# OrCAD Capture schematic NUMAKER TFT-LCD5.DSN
size A4; title: NuMaker TFT-LCD5; rev: 1.0; company: nuvoTon Technology Corp.; note: LCD
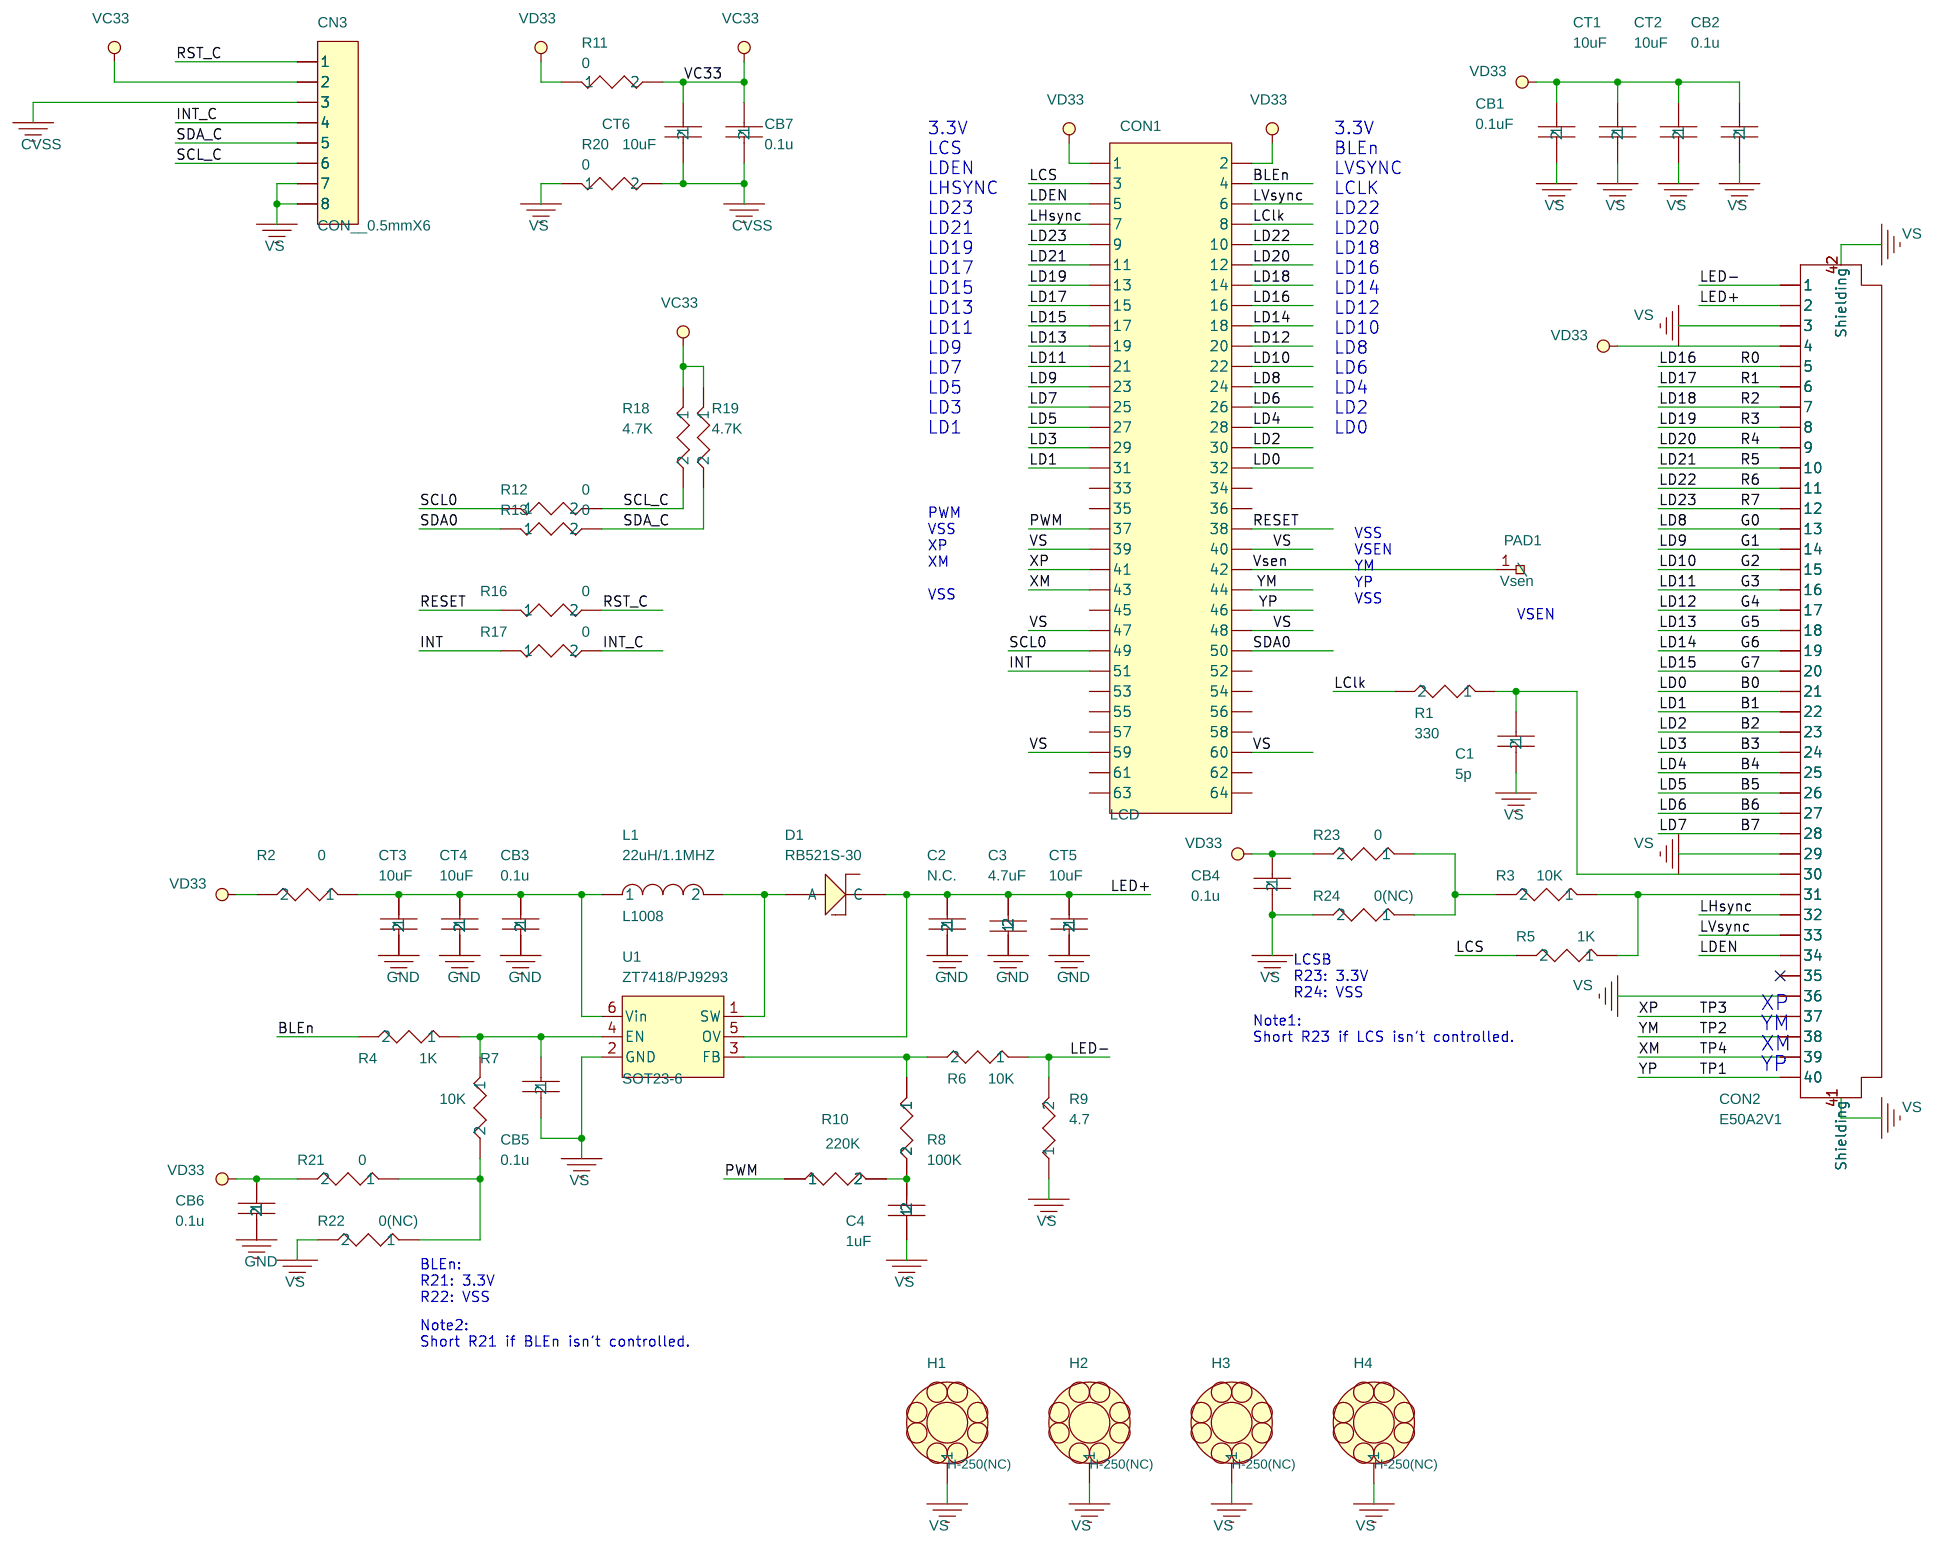
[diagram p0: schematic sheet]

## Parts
C1  5p  [C0603]
C2  N.C.  [C0603]
C3  4.7uF  [C0603]
C4  1uF  [C0603]
CB1  0.1uF  [C0603]
CB2  0.1u  [C0603]
CB3  0.1u  [C0603]
CB4  0.1u  [C0603]
CB5  0.1u  [C0603]
CB6  0.1u  [C0603]
CB7  0.1u  [C0603]
CN3  CON__0.5mmX6  [CON_0.5MMX6]
CON1  LCD  [F_DIN_32X2/2.54A]
CON2  E50A2V1  [CON0.5mmx40]
CT1  10uF  [C0603]
CT2  10uF  [C0603]
CT3  10uF  [C0603]
CT4  10uF  [C0603]
CT5  10uF  [C0603]
CT6  10uF  [C0603]
D1  RB521S-30  [Diode_A]
H1  H-250(NC)  [H-250]
H2  H-250(NC)  [H-250]
H3  H-250(NC)  [H-250]
H4  H-250(NC)  [H-250]
L1  22uH/1.1MHZ  [L1008]
PAD1  Vsen  [1PAD_1.25X1.25MM]
R1  330  [R0603]
R2  0  [R0603]
R3  10K  [R0603]
R4  1K  [R0603]
R5  1K  [R0603]
R6  10K  [R0603]
R7  10K  [R0603]
R8  100K  [R0603]
R9  4.7  [R0603]
R10  220K  [R0603]
R11  0  [R0603]
R12  0  [R0603]
R13  0  [R0603]
R16  0  [R0603]
R17  0  [R0603]
R18  4.7K  [R0603]
R19  4.7K  [R0603]
R20  0  [R0603]
R21  0  [R0603]
R22  0(NC)  [R0603]
R23  0  [R0603]
R24  0(NC)  [R0603]
U1  ZT7418/PJ9293  [SOT23-6]

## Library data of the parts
C1 = CAP-B_2: Package: 0603
C2 = CAP-B_5: Package: C0402
C3 = CAP_NP_6
C4 = CAP_NP_4
CB1 = CAP_NP
CB2 = CAP_NP_9
CB3 = CAP-B_3: Package: C0402
CB4 = CAP-B: Package: C0402
CB5 = CAP-B_1: Package: C0402
CB6 = CAP-B_4: Package: C0402
CB7 = CAP_NP_2
CN3 = CON8
CON1 = CON40A_0
CON2 = LCMCON40x1
CT1 = CAP_NP_8
CT2 = CAP_NP_3
CT3 = CAP_NP_7
CT4 = CAP_NP_1
CT5 = CAP-B_6: Package: C0402
CT6 = CAP_NP_5
D1 = ZENAR_0: Package: D
H1-H4 = T_POINT_2
L1 = INDUCTOR: Package: L-3
PAD1 = 1PAD_0
R1 = R
R2 = R_12: Package: R0402
R3 = R_20: Package: R0402
R4 = R_10: Package: R0402
R5 = R_14: Package: R0402
R6 = R_13: Package: R0402
R7 = R_2: Package: R0402
R8 = R_3
R9 = R_1: Package: R0402
R10 = R_9
R11 = R_8
R12 = R_5
R13 = R_4
R16 = R_19
R17 = R_18
R18 = R_17
R19 = R_16
R20 = R_11
R21 = R_6: Package: R0402
R22 = R_7: Package: R0402
R23 = R_15: Package: R0402
R24 = R_21: Package: R0402
U1 = PJ9293

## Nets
B0: CON1.32 CON2.21
B1: CON1.31 CON2.22
B2: CON1.30 CON2.23
B3: CON1.29 CON2.24
B4: CON1.28 CON2.25
B5: CON1.27 CON2.26
B6: CON1.26 CON2.27
B7: CON1.25 CON2.28
BLEn: CON1.4 R4.2
CVSS: CB7.2 CN3.3 CT6.2 R20.2
G0: CON1.24 CON2.13
G1: CON1.23 CON2.14
G2: CON1.22 CON2.15
G3: CON1.21 CON2.16
G4: CON1.20 CON2.17
G5: CON1.19 CON2.18
G6: CON1.18 CON2.19
G7: CON1.17 CON2.20
INT: CON1.51 R17.1
INT_C: CN3.4 R17.2
LClk: CON1.8 R1.2
LCS: CON1.3 R5.2
LD16: CON1.16 CON2.5
LD17: CON1.15 CON2.6
LD18: CON1.14 CON2.7
LD19: CON1.13 CON2.8
LD20: CON1.12 CON2.9
LD21: CON1.11 CON2.10
LD22: CON1.10 CON2.11
LD23: CON1.9 CON2.12
LDEN: CON1.5 CON2.34
LED+: C2.1 C3.2 CON2.2 CT5.1 D1.2(C) U1.5(OV)
LED-: CON2.1 R6.1 R9.2
LHsync: CON1.7 CON2.32
LVsync: CON1.6 CON2.33
PWM: CON1.37 R10.1
RESET: CON1.38 R16.1
RST_C: CN3.1 R16.2
SCL0: CON1.49 R12.1
SCL_C: CN3.6 R12.2 R18.2
SDA0: CON1.50 R13.1
SDA_C: CN3.5 R13.2 R19.2
TP1: CON1.46 CON2.40
TP2: CON1.44 CON2.38
TP3: CON1.41 CON2.37
TP4: CON1.43 CON2.39
VC33: CB7.1 CN3.2 CT6.1 R11.2 R18.1 R19.1
VD33: CB1.1 CB2.1 CB4.1 CB6.1 CON1.1 CON1.2 CON2.4 CT1.1 CT2.1 R2.2 R11.1 R21.2 R23.2
VS: C1.2 C2.2 C3.1 C4.1 CB1.2 CB2.2 CB3.2 CB4.2 CB5.2 CB6.2 CN3.7 CN3.8 CON1.39 CON1.40 CON1.47 CON1.48 CON1.59 CON1.60 CON2.3 CON2.29 CON2.36 CON2.41(Shielding) CON2.42(Shielding) CT1.2 CT2.2 CT3.2 CT4.2 CT5.2 H1.1 H2.1 H3.1 H4.1 R9.1 R20.1 R22.2 R24.2 U1.2(GND)
Vsen: CON1.42 PAD1.1(\)
N16195231: C1.1 CON2.30 R1.1
N16195511: CON2.31 R3.1 R5.1
N16195927: R3.2 R23.1 R24.1
N16198209: CB5.1 R4.1 R7.1 U1.4(EN)
N16198213: CB3.1 CT3.1 CT4.1 L1.1 R2.1 U1.6(Vin)
N16198391: R6.2 R8.1 U1.3(FB)
N16198395: C4.2 R8.2 R10.2
N16198399: R7.2 R21.1 R22.1
N16198443: D1.1(A) L1.2 U1.1(SW)

Not connected (* = marked no-connect by the designer): CON1 33 34 35 36 45 52 53 54 55 56 57 58 61 62 63 64; CON2 35*

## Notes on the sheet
- 3.3V
  LCS
  LDEN
  LHSYNC
  LD23
  LD21
  LD19
  LD17
  LD15
  LD13
  LD11
  LD9
  LD7
  LD5
  LD3
  LD1
- 3.3V
  BLEn
  LVSYNC
  LCLK
  LD22
  LD20
  LD18
  LD16
  LD14
  LD12
  LD10
  LD8
  LD6
  LD4
  LD2
  LD0
- PWM
  VSS
  XP
  XM
  VSS
- VSS
  VSEN
  YM
  YP
  VSS
- VSEN
- LCSB
  R23: 3.3V
  R24: VSS
- Note1:
  Short R23 if LCS isn't controlled.
- XP
- YM
- XM
- YP
- BLEn:
  R21: 3.3V
  R22: VSS
- Note2:
  Short R21 if BLEn isn't controlled.
